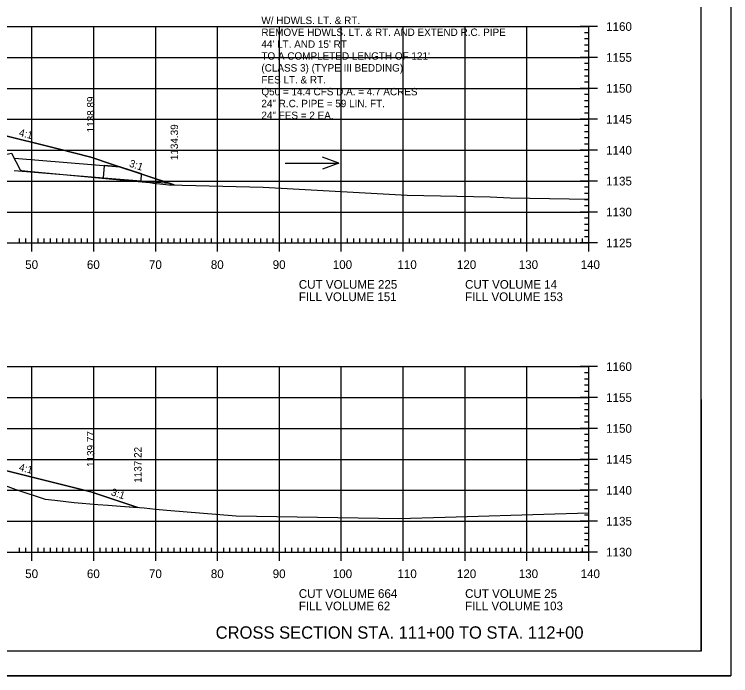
# Model space of a CAD drawing. Extents: x 1322838 to 1324533, y 339903 to 351025.
# Drawn here: x 1323750.9 to 1323866.6, y 340116.5 to 340223.4 of the extents above; entities that cross this region are included whole.
import ezdxf

# ---------------------------------------------------------------- set-up
doc = ezdxf.new("R2010")
doc.units = 0
for name, color, linetype in [('1', 7, 'Continuous'), ('R_Axis', 7, 'Continuous'), ('R_Axis Annot', 7, 'Continuous'), ('R_Border', 7, 'Continuous'), ('R_Border Notes', 7, 'Continuous'), ('R_Draft', 7, 'Continuous'), ('R_Exist Surface', 7, 'Continuous'), ('R_Fin Surface', 7, 'Continuous'), ('R_Fin Surface Annot', 7, 'Continuous'), ('R_Grid', 7, 'Continuous'), ('R_No Plot', 7, 'Continuous'), ('R_Water', 7, 'Continuous'), ('R_Water Annot', 7, 'Continuous')]:
    doc.layers.add(name, color=color, linetype=linetype)

msp = doc.modelspace()

# ---------------------------------------------------------------- linework, layer by layer
at = {"layer": '1'}
msp.add_lwpolyline([(1323765.41, 340198.97), (1323765.25, 340196.98), (1323771.35, 340196.48), (1323771.44, 340197.61), (1323767.9, 340198.77)], close=True, dxfattribs=at)
at = {"layer": 'R_Axis'}
for p, q in [((1323845.12, 340221.44), (1323842.32, 340221.44)), ((1323843.72, 340186.44), (1323843.72, 340221.44)), ((1323843.72, 340220.44), (1323843.02, 340220.44)), ((1323843.72, 340219.44), (1323843.02, 340219.44)), ((1323843.72, 340218.44), (1323843.02, 340218.44)), ((1323843.72, 340217.44), (1323843.02, 340217.44)), ((1323845.12, 340216.44), (1323842.32, 340216.44)), ((1323843.72, 340215.44), (1323843.02, 340215.44)), ((1323843.72, 340214.44), (1323843.02, 340214.44)), ((1323843.72, 340213.44), (1323843.02, 340213.44)), ((1323843.72, 340212.44), (1323843.02, 340212.44)), ((1323845.12, 340211.44), (1323842.32, 340211.44)), ((1323843.72, 340210.44), (1323843.02, 340210.44)), ((1323843.72, 340209.44), (1323843.02, 340209.44)), ((1323843.72, 340208.44), (1323843.02, 340208.44)), ((1323843.72, 340207.44), (1323843.02, 340207.44)), ((1323845.12, 340206.44), (1323842.32, 340206.44)), ((1323843.72, 340205.44), (1323843.02, 340205.44)), ((1323843.72, 340204.44), (1323843.02, 340204.44)), ((1323843.72, 340203.44), (1323843.02, 340203.44)), ((1323845.12, 340201.44), (1323842.32, 340201.44)), ((1323843.72, 340202.44), (1323843.02, 340202.44)), ((1323843.72, 340200.44), (1323843.02, 340200.44)), ((1323843.72, 340199.44), (1323843.02, 340199.44)), ((1323843.72, 340198.44), (1323843.02, 340198.44)), ((1323843.72, 340197.44), (1323843.02, 340197.44)), ((1323845.12, 340196.44), (1323842.32, 340196.44)), ((1323843.72, 340195.44), (1323843.02, 340195.44)), ((1323843.72, 340194.44), (1323843.02, 340194.44)), ((1323843.72, 340193.44), (1323843.02, 340193.44)), ((1323843.72, 340192.44), (1323843.02, 340192.44)), ((1323845.12, 340191.44), (1323842.32, 340191.44)), ((1323843.72, 340190.44), (1323843.02, 340190.44)), ((1323843.72, 340189.44), (1323843.02, 340189.44)), ((1323753.72, 340185.04), (1323753.72, 340187.84)), ((1323763.72, 340185.04), (1323763.72, 340187.84)), ((1323773.72, 340185.04), (1323773.72, 340187.84)), ((1323783.72, 340185.04), (1323783.72, 340187.84)), ((1323793.72, 340185.04), (1323793.72, 340187.84)), ((1323803.72, 340185.04), (1323803.72, 340187.84)), ((1323813.72, 340185.04), (1323813.72, 340187.84)), ((1323823.72, 340185.04), (1323823.72, 340187.84)), ((1323833.72, 340185.04), (1323833.72, 340187.84)), ((1323843.72, 340188.44), (1323843.02, 340188.44)), ((1323843.72, 340185.04), (1323843.72, 340187.84)), ((1323563.72, 340186.44), (1323843.72, 340186.44)), ((1323751.72, 340186.44), (1323751.72, 340187.14)), ((1323752.72, 340186.44), (1323752.72, 340187.14)), ((1323754.72, 340186.44), (1323754.72, 340187.14)), ((1323755.72, 340186.44), (1323755.72, 340187.14)), ((1323756.72, 340186.44), (1323756.72, 340187.14)), ((1323757.72, 340186.44), (1323757.72, 340187.14)), ((1323758.72, 340186.44), (1323758.72, 340187.14)), ((1323759.72, 340186.44), (1323759.72, 340187.14)), ((1323760.72, 340186.44), (1323760.72, 340187.14)), ((1323761.72, 340186.44), (1323761.72, 340187.14)), ((1323762.72, 340186.44), (1323762.72, 340187.14)), ((1323764.72, 340186.44), (1323764.72, 340187.14)), ((1323765.72, 340186.44), (1323765.72, 340187.14)), ((1323766.72, 340186.44), (1323766.72, 340187.14)), ((1323767.72, 340186.44), (1323767.72, 340187.14)), ((1323768.72, 340186.44), (1323768.72, 340187.14)), ((1323769.72, 340186.44), (1323769.72, 340187.14)), ((1323770.72, 340186.44), (1323770.72, 340187.14)), ((1323771.72, 340186.44), (1323771.72, 340187.14)), ((1323772.72, 340186.44), (1323772.72, 340187.14)), ((1323774.72, 340186.44), (1323774.72, 340187.14)), ((1323775.72, 340186.44), (1323775.72, 340187.14)), ((1323776.72, 340186.44), (1323776.72, 340187.14)), ((1323777.72, 340186.44), (1323777.72, 340187.14)), ((1323778.72, 340186.44), (1323778.72, 340187.14)), ((1323779.72, 340186.44), (1323779.72, 340187.14)), ((1323780.72, 340186.44), (1323780.72, 340187.14)), ((1323781.72, 340186.44), (1323781.72, 340187.14)), ((1323782.72, 340186.44), (1323782.72, 340187.14)), ((1323784.72, 340186.44), (1323784.72, 340187.14)), ((1323785.72, 340186.44), (1323785.72, 340187.14)), ((1323786.72, 340186.44), (1323786.72, 340187.14)), ((1323787.72, 340186.44), (1323787.72, 340187.14)), ((1323788.72, 340186.44), (1323788.72, 340187.14)), ((1323789.72, 340186.44), (1323789.72, 340187.14)), ((1323790.72, 340186.44), (1323790.72, 340187.14)), ((1323791.72, 340186.44), (1323791.72, 340187.14)), ((1323792.72, 340186.44), (1323792.72, 340187.14)), ((1323794.72, 340186.44), (1323794.72, 340187.14)), ((1323795.72, 340186.44), (1323795.72, 340187.14)), ((1323796.72, 340186.44), (1323796.72, 340187.14)), ((1323797.72, 340186.44), (1323797.72, 340187.14)), ((1323798.72, 340186.44), (1323798.72, 340187.14)), ((1323799.72, 340186.44), (1323799.72, 340187.14)), ((1323800.72, 340186.44), (1323800.72, 340187.14)), ((1323801.72, 340186.44), (1323801.72, 340187.14)), ((1323802.72, 340186.44), (1323802.72, 340187.14)), ((1323804.72, 340186.44), (1323804.72, 340187.14)), ((1323805.72, 340186.44), (1323805.72, 340187.14)), ((1323806.72, 340186.44), (1323806.72, 340187.14)), ((1323807.72, 340186.44), (1323807.72, 340187.14)), ((1323808.72, 340186.44), (1323808.72, 340187.14)), ((1323809.72, 340186.44), (1323809.72, 340187.14)), ((1323810.72, 340186.44), (1323810.72, 340187.14)), ((1323811.72, 340186.44), (1323811.72, 340187.14)), ((1323812.72, 340186.44), (1323812.72, 340187.14)), ((1323814.72, 340186.44), (1323814.72, 340187.14)), ((1323815.72, 340186.44), (1323815.72, 340187.14)), ((1323816.72, 340186.44), (1323816.72, 340187.14)), ((1323817.72, 340186.44), (1323817.72, 340187.14)), ((1323818.72, 340186.44), (1323818.72, 340187.14)), ((1323819.72, 340186.44), (1323819.72, 340187.14)), ((1323820.72, 340186.44), (1323820.72, 340187.14)), ((1323821.72, 340186.44), (1323821.72, 340187.14)), ((1323822.72, 340186.44), (1323822.72, 340187.14)), ((1323824.72, 340186.44), (1323824.72, 340187.14)), ((1323825.72, 340186.44), (1323825.72, 340187.14)), ((1323826.72, 340186.44), (1323826.72, 340187.14)), ((1323827.72, 340186.44), (1323827.72, 340187.14)), ((1323828.72, 340186.44), (1323828.72, 340187.14)), ((1323829.72, 340186.44), (1323829.72, 340187.14)), ((1323830.72, 340186.44), (1323830.72, 340187.14)), ((1323831.72, 340186.44), (1323831.72, 340187.14)), ((1323832.72, 340186.44), (1323832.72, 340187.14)), ((1323834.72, 340186.44), (1323834.72, 340187.14)), ((1323835.72, 340186.44), (1323835.72, 340187.14)), ((1323836.72, 340186.44), (1323836.72, 340187.14)), ((1323837.72, 340186.44), (1323837.72, 340187.14)), ((1323838.72, 340186.44), (1323838.72, 340187.14)), ((1323839.72, 340186.44), (1323839.72, 340187.14)), ((1323840.72, 340186.44), (1323840.72, 340187.14)), ((1323841.72, 340186.44), (1323841.72, 340187.14)), ((1323845.12, 340186.44), (1323842.32, 340186.44)), ((1323842.72, 340186.44), (1323842.72, 340187.14)), ((1323843.72, 340187.44), (1323843.02, 340187.44)), ((1323845.12, 340166.44), (1323842.32, 340166.44)), ((1323843.72, 340136.44), (1323843.72, 340166.44)), ((1323843.72, 340165.44), (1323843.02, 340165.44)), ((1323843.72, 340164.44), (1323843.02, 340164.44)), ((1323843.72, 340163.44), (1323843.02, 340163.44)), ((1323843.72, 340162.44), (1323843.02, 340162.44)), ((1323845.12, 340161.44), (1323842.32, 340161.44)), ((1323843.72, 340160.44), (1323843.02, 340160.44)), ((1323843.72, 340159.44), (1323843.02, 340159.44)), ((1323843.72, 340158.44), (1323843.02, 340158.44)), ((1323843.72, 340157.44), (1323843.02, 340157.44)), ((1323845.12, 340156.44), (1323842.32, 340156.44)), ((1323843.72, 340155.44), (1323843.02, 340155.44)), ((1323843.72, 340154.44), (1323843.02, 340154.44)), ((1323843.72, 340153.44), (1323843.02, 340153.44)), ((1323843.72, 340152.44), (1323843.02, 340152.44)), ((1323845.12, 340151.44), (1323842.32, 340151.44)), ((1323843.72, 340150.44), (1323843.02, 340150.44)), ((1323843.72, 340149.44), (1323843.02, 340149.44)), ((1323843.72, 340148.44), (1323843.02, 340148.44)), ((1323843.72, 340147.44), (1323843.02, 340147.44)), ((1323845.12, 340146.44), (1323842.32, 340146.44)), ((1323843.72, 340145.44), (1323843.02, 340145.44)), ((1323843.72, 340144.44), (1323843.02, 340144.44)), ((1323843.72, 340143.44), (1323843.02, 340143.44)), ((1323843.72, 340142.44), (1323843.02, 340142.44)), ((1323845.12, 340141.44), (1323842.32, 340141.44)), ((1323843.72, 340140.44), (1323843.02, 340140.44)), ((1323843.72, 340139.44), (1323843.02, 340139.44)), ((1323753.72, 340135.04), (1323753.72, 340137.84)), ((1323763.72, 340135.04), (1323763.72, 340137.84)), ((1323773.72, 340135.04), (1323773.72, 340137.84)), ((1323783.72, 340135.04), (1323783.72, 340137.84)), ((1323793.72, 340135.04), (1323793.72, 340137.84)), ((1323803.72, 340135.04), (1323803.72, 340137.84)), ((1323813.72, 340135.04), (1323813.72, 340137.84)), ((1323823.72, 340135.04), (1323823.72, 340137.84)), ((1323833.72, 340135.04), (1323833.72, 340137.84)), ((1323843.72, 340138.44), (1323843.02, 340138.44)), ((1323843.72, 340135.04), (1323843.72, 340137.84)), ((1323751.72, 340136.44), (1323751.72, 340137.14)), ((1323752.72, 340136.44), (1323752.72, 340137.14)), ((1323754.72, 340136.44), (1323754.72, 340137.14)), ((1323755.72, 340136.44), (1323755.72, 340137.14)), ((1323756.72, 340136.44), (1323756.72, 340137.14)), ((1323757.72, 340136.44), (1323757.72, 340137.14)), ((1323758.72, 340136.44), (1323758.72, 340137.14)), ((1323759.72, 340136.44), (1323759.72, 340137.14)), ((1323760.72, 340136.44), (1323760.72, 340137.14)), ((1323761.72, 340136.44), (1323761.72, 340137.14)), ((1323762.72, 340136.44), (1323762.72, 340137.14)), ((1323764.72, 340136.44), (1323764.72, 340137.14)), ((1323765.72, 340136.44), (1323765.72, 340137.14)), ((1323766.72, 340136.44), (1323766.72, 340137.14)), ((1323767.72, 340136.44), (1323767.72, 340137.14)), ((1323768.72, 340136.44), (1323768.72, 340137.14)), ((1323769.72, 340136.44), (1323769.72, 340137.14)), ((1323770.72, 340136.44), (1323770.72, 340137.14)), ((1323771.72, 340136.44), (1323771.72, 340137.14)), ((1323772.72, 340136.44), (1323772.72, 340137.14)), ((1323774.72, 340136.44), (1323774.72, 340137.14)), ((1323775.72, 340136.44), (1323775.72, 340137.14)), ((1323776.72, 340136.44), (1323776.72, 340137.14)), ((1323777.72, 340136.44), (1323777.72, 340137.14)), ((1323778.72, 340136.44), (1323778.72, 340137.14)), ((1323779.72, 340136.44), (1323779.72, 340137.14)), ((1323780.72, 340136.44), (1323780.72, 340137.14)), ((1323781.72, 340136.44), (1323781.72, 340137.14)), ((1323782.72, 340136.44), (1323782.72, 340137.14)), ((1323784.72, 340136.44), (1323784.72, 340137.14)), ((1323785.72, 340136.44), (1323785.72, 340137.14)), ((1323786.72, 340136.44), (1323786.72, 340137.14)), ((1323787.72, 340136.44), (1323787.72, 340137.14)), ((1323788.72, 340136.44), (1323788.72, 340137.14)), ((1323789.72, 340136.44), (1323789.72, 340137.14)), ((1323790.72, 340136.44), (1323790.72, 340137.14)), ((1323791.72, 340136.44), (1323791.72, 340137.14)), ((1323792.72, 340136.44), (1323792.72, 340137.14)), ((1323794.72, 340136.44), (1323794.72, 340137.14)), ((1323795.72, 340136.44), (1323795.72, 340137.14)), ((1323796.72, 340136.44), (1323796.72, 340137.14)), ((1323797.72, 340136.44), (1323797.72, 340137.14)), ((1323798.72, 340136.44), (1323798.72, 340137.14)), ((1323799.72, 340136.44), (1323799.72, 340137.14)), ((1323800.72, 340136.44), (1323800.72, 340137.14)), ((1323801.72, 340136.44), (1323801.72, 340137.14)), ((1323802.72, 340136.44), (1323802.72, 340137.14)), ((1323804.72, 340136.44), (1323804.72, 340137.14)), ((1323805.72, 340136.44), (1323805.72, 340137.14)), ((1323806.72, 340136.44), (1323806.72, 340137.14)), ((1323807.72, 340136.44), (1323807.72, 340137.14)), ((1323808.72, 340136.44), (1323808.72, 340137.14)), ((1323809.72, 340136.44), (1323809.72, 340137.14)), ((1323810.72, 340136.44), (1323810.72, 340137.14)), ((1323811.72, 340136.44), (1323811.72, 340137.14)), ((1323812.72, 340136.44), (1323812.72, 340137.14)), ((1323814.72, 340136.44), (1323814.72, 340137.14)), ((1323815.72, 340136.44), (1323815.72, 340137.14)), ((1323816.72, 340136.44), (1323816.72, 340137.14)), ((1323817.72, 340136.44), (1323817.72, 340137.14)), ((1323818.72, 340136.44), (1323818.72, 340137.14)), ((1323819.72, 340136.44), (1323819.72, 340137.14)), ((1323820.72, 340136.44), (1323820.72, 340137.14)), ((1323821.72, 340136.44), (1323821.72, 340137.14)), ((1323822.72, 340136.44), (1323822.72, 340137.14)), ((1323824.72, 340136.44), (1323824.72, 340137.14)), ((1323825.72, 340136.44), (1323825.72, 340137.14)), ((1323826.72, 340136.44), (1323826.72, 340137.14)), ((1323827.72, 340136.44), (1323827.72, 340137.14)), ((1323828.72, 340136.44), (1323828.72, 340137.14)), ((1323829.72, 340136.44), (1323829.72, 340137.14)), ((1323830.72, 340136.44), (1323830.72, 340137.14)), ((1323831.72, 340136.44), (1323831.72, 340137.14)), ((1323832.72, 340136.44), (1323832.72, 340137.14)), ((1323834.72, 340136.44), (1323834.72, 340137.14)), ((1323835.72, 340136.44), (1323835.72, 340137.14)), ((1323836.72, 340136.44), (1323836.72, 340137.14)), ((1323837.72, 340136.44), (1323837.72, 340137.14)), ((1323838.72, 340136.44), (1323838.72, 340137.14)), ((1323839.72, 340136.44), (1323839.72, 340137.14)), ((1323840.72, 340136.44), (1323840.72, 340137.14)), ((1323841.72, 340136.44), (1323841.72, 340137.14)), ((1323842.72, 340136.44), (1323842.72, 340137.14)), ((1323843.72, 340137.44), (1323843.02, 340137.44)), ((1323563.72, 340136.44), (1323843.72, 340136.44)), ((1323845.12, 340136.44), (1323842.32, 340136.44))]:
    msp.add_line(p, q, dxfattribs=at)
at = {"layer": 'R_Border'}
for q in [(1323861.9, 340325.9), (1323545.72, 340120.44)]:
    msp.add_line((1323861.9, 340120.44), q, dxfattribs=at)
at = {"layer": 'R_Exist Surface'}
for points in [[(1323750.42, 340200.99), (1323751.79, 340198.28), (1323752.16, 340198.1), (1323752.39, 340198.08), (1323752.48, 340198.09), (1323752.56, 340198.09), (1323753.08, 340198.03), (1323769.67, 340196.51), (1323772.79, 340196.21), (1323773.38, 340196.13), (1323774.86, 340195.93), (1323775.82, 340195.85), (1323791.09, 340195.44), (1323814.35, 340194.19), (1323827.78, 340193.89), (1323831.03, 340193.75), (1323843.72, 340193.52)], [(1323742.97, 340149.6), (1323751.09, 340146.58), (1323755.88, 340144.99), (1323757.43, 340144.83), (1323760.52, 340144.44), (1323764.39, 340144.15), (1323766.05, 340144.04), (1323768.05, 340143.88), (1323771.88, 340143.58), (1323773.67, 340143.38), (1323775.54, 340143.22), (1323786.74, 340142.3), (1323813.03, 340141.89), (1323820.49, 340142.11), (1323838.22, 340142.64), (1323843.72, 340142.79)]]:
    msp.add_lwpolyline(points, dxfattribs=at)
at = {"layer": 'R_Fin Surface'}
for points in [[(1323747.94, 340204.15), (1323757.94, 340201.65), (1323763.22, 340200.33), (1323766.92, 340199.1), (1323776.73, 340195.83)], [(1323620.93, 340151.79), (1323620.93, 340151.79), (1323639.68, 340145.54), (1323641.88, 340146.27), (1323644.22, 340147.05), (1323651.51, 340148.27), (1323656.81, 340149.15), (1323662.16, 340150.04), (1323666.22, 340150.72), (1323668.71, 340150.82), (1323672.22, 340150.96), (1323673.09, 340150.98), (1323674.22, 340151), (1323703.72, 340151.59), (1323733.22, 340151.68), (1323733.6, 340151.68), (1323735.22, 340151.69), (1323737.64, 340151.7), (1323741.22, 340151.71), (1323748.34, 340149.93), (1323763.22, 340146.21), (1323770.84, 340143.66)]]:
    msp.add_lwpolyline(points, dxfattribs=at)
at = {"layer": 'R_Grid'}
for p, q in [((1323563.72, 340221.44), (1323843.72, 340221.44)), ((1323753.72, 340186.44), (1323753.72, 340221.44)), ((1323763.72, 340186.44), (1323763.72, 340221.44)), ((1323773.72, 340186.44), (1323773.72, 340221.44)), ((1323783.72, 340186.44), (1323783.72, 340221.44)), ((1323793.72, 340186.44), (1323793.72, 340221.44)), ((1323803.72, 340186.44), (1323803.72, 340221.44)), ((1323813.72, 340186.44), (1323813.72, 340221.44)), ((1323823.72, 340186.44), (1323823.72, 340221.44)), ((1323833.72, 340186.44), (1323833.72, 340221.44)), ((1323843.72, 340186.44), (1323843.72, 340221.44)), ((1323563.72, 340216.44), (1323843.72, 340216.44)), ((1323563.72, 340211.44), (1323843.72, 340211.44)), ((1323563.72, 340206.44), (1323843.72, 340206.44)), ((1323563.72, 340201.44), (1323843.72, 340201.44)), ((1323563.72, 340196.44), (1323843.72, 340196.44)), ((1323563.72, 340191.44), (1323843.72, 340191.44)), ((1323563.72, 340186.44), (1323843.72, 340186.44)), ((1323563.72, 340166.44), (1323843.72, 340166.44)), ((1323753.72, 340136.44), (1323753.72, 340166.44)), ((1323763.72, 340136.44), (1323763.72, 340166.44)), ((1323773.72, 340136.44), (1323773.72, 340166.44)), ((1323783.72, 340136.44), (1323783.72, 340166.44)), ((1323793.72, 340136.44), (1323793.72, 340166.44)), ((1323803.72, 340136.44), (1323803.72, 340166.44)), ((1323813.72, 340136.44), (1323813.72, 340166.44)), ((1323823.72, 340136.44), (1323823.72, 340166.44)), ((1323833.72, 340136.44), (1323833.72, 340166.44)), ((1323843.72, 340136.44), (1323843.72, 340166.44)), ((1323563.72, 340161.44), (1323843.72, 340161.44)), ((1323563.72, 340156.44), (1323843.72, 340156.44)), ((1323563.72, 340151.44), (1323843.72, 340151.44)), ((1323563.72, 340146.44), (1323843.72, 340146.44)), ((1323563.72, 340141.44), (1323843.72, 340141.44)), ((1323563.72, 340136.44), (1323843.72, 340136.44))]:
    msp.add_line(p, q, dxfattribs=at)
at = {"layer": 'R_No Plot'}
msp.add_line((1323533.31, 340116.46), (1323866.65, 340116.46), dxfattribs=at)
for points in [[(1323533.31, 340329.8), (1323866.65, 340329.8), (1323866.65, 340116.46), (1323533.31, 340116.46)], [(1323779.64, 340325.9), (1323799.26, 340325.9), (1323799.26, 340316.02), (1323815.37, 340316.02), (1323838.57, 340316.02), (1323838.57, 340283.35), (1323861.77, 340283.35), (1323861.9, 340120.44), (1323545.72, 340120.44), (1323545.72, 340325.9)], [(1323740.24, 340204.31), (1323742.62, 340203.74), (1323744.42, 340202.84), (1323749.19, 340200.7), (1323749.93, 340200.87), (1323750.42, 340200.99), (1323751.79, 340198.28), (1323752.16, 340198.1), (1323752.39, 340198.08), (1323752.48, 340198.09), (1323752.56, 340198.09), (1323753.08, 340198.03), (1323769.67, 340196.51), (1323772.79, 340196.21), (1323773.38, 340196.13), (1323774.86, 340195.93), (1323775.82, 340195.85), (1323776.73, 340195.83), (1323766.92, 340199.1), (1323763.22, 340200.33), (1323757.94, 340201.65), (1323747.94, 340204.15), (1323747.94, 340204.15)], [(1323740.7, 340150.08), (1323742.97, 340149.6), (1323751.09, 340146.58), (1323755.88, 340144.99), (1323757.43, 340144.83), (1323760.52, 340144.44), (1323764.39, 340144.15), (1323766.05, 340144.04), (1323768.05, 340143.88), (1323770.84, 340143.66), (1323763.22, 340146.21), (1323748.34, 340149.93)]]:
    msp.add_lwpolyline(points, close=True, dxfattribs=at)
at = {"layer": 'R_Water'}
for p, q in [((1323750.89, 340200.15), (1323767.9, 340198.77)), ((1323750.86, 340198.15), (1323775.84, 340196.12))]:
    msp.add_line(p, q, dxfattribs=at)
at = {"layer": 'R_Water Annot'}
for p, q in [((1323803.33, 340199.33), (1323800.67, 340200.3)), ((1323794.63, 340199.33), (1323803.33, 340199.33)), ((1323803.33, 340199.33), (1323800.67, 340198.36))]:
    msp.add_line(p, q, dxfattribs=at)

# ---------------------------------------------------------------- texts
at = {"layer": 'R_Axis Annot'}
for s, p in [('1160', (1323846.52, 340220.74)), ('1155', (1323846.52, 340215.74)), ('1150', (1323846.52, 340210.74)), ('1145', (1323846.52, 340205.74)), ('1140', (1323846.52, 340200.74)), ('1135', (1323846.52, 340195.74)), ('1130', (1323846.52, 340190.74)), ('1125', (1323846.52, 340185.74)), ('50', (1323752.63, 340182.24)), ('60', (1323762.6, 340182.24)), ('70', (1323772.63, 340182.24)), ('80', (1323782.63, 340182.24)), ('90', (1323792.63, 340182.24)), ('100', (1323802.34, 340182.24)), ('110', (1323812.79, 340182.24)), ('120', (1323822.4, 340182.24)), ('130', (1323832.4, 340182.24)), ('140', (1323842.4, 340182.24)), ('CUT VOLUME 225', (1323796.85, 340179.04)), ('CUT VOLUME 14', (1323823.72, 340179.04)), ('FILL VOLUME 151', (1323796.85, 340177.04)), ('FILL VOLUME 153', (1323823.72, 340177.04)), ('1160', (1323846.52, 340165.74)), ('1155', (1323846.52, 340160.74)), ('1150', (1323846.52, 340155.74)), ('1145', (1323846.52, 340150.74)), ('1140', (1323846.52, 340145.74)), ('1135', (1323846.52, 340140.74)), ('1130', (1323846.52, 340135.74)), ('50', (1323752.63, 340132.24)), ('60', (1323762.6, 340132.24)), ('70', (1323772.63, 340132.24)), ('80', (1323782.63, 340132.24)), ('90', (1323792.63, 340132.24)), ('100', (1323802.34, 340132.24)), ('110', (1323812.79, 340132.24)), ('120', (1323822.4, 340132.24)), ('130', (1323832.4, 340132.24)), ('140', (1323842.4, 340132.24)), ('CUT VOLUME 664', (1323796.85, 340129.04)), ('CUT VOLUME 25', (1323823.72, 340129.04)), ('FILL VOLUME 62', (1323796.85, 340127.04)), ('FILL VOLUME 103', (1323823.72, 340127.04))]:
    msp.add_text(s, height=1.4, dxfattribs=at).set_placement(p)
at = {"layer": 'R_Border Notes'}
for s, p in [('W/ HDWLS. LT. & RT.', (1323790.8, 340221.84)), ('REMOVE HDWLS. LT. & RT. AND EXTEND R.C. PIPE', (1323790.8, 340219.92)), ("44' LT. AND 15' RT", (1323790.8, 340218)), ("TO A COMPLETED LENGTH OF 121'", (1323790.8, 340216.08)), ('(CLASS 3) (TYPE III BEDDING)', (1323790.8, 340214.16)), ('FES LT. & RT.  ', (1323790.8, 340212.24)), ('Q50 = 14.4 CFS D.A. = 4.7 ACRES', (1323790.8, 340210.32)), ('24" R.C. PIPE = 59 LIN. FT.', (1323790.8, 340208.4)), ('24" FES = 2 EA.', (1323790.8, 340206.48))]:
    msp.add_text(s, height=1.2, dxfattribs=at).set_placement(p)
at = {"layer": 'R_Draft'}
msp.add_text('CROSS SECTION STA. 111+00 TO STA. 112+00', height=2, dxfattribs=at).set_placement((1323783.41, 340122.44))
at = {"layer": 'R_Fin Surface Annot'}
for s, rotation, p in [('1138.89', 90, (1323763.82, 340204.33)), ('1134.39', 90, (1323777.33, 340199.83)), ('4:1', 345.9638, (1323751.53, 340203.77)), ('3:1', 341.5638, (1323769.34, 340198.82)), ('1139.77', 90, (1323763.82, 340150.21)), ('1137.22', 90, (1323771.44, 340147.66)), ('4:1', 345.9638, (1323751.53, 340149.64)), ('3:1', 341.5583, (1323766.4, 340145.67))]:
    msp.add_text(s, height=1.2, rotation=rotation, dxfattribs=at).set_placement(p)

doc.saveas('drawing.dxf')
